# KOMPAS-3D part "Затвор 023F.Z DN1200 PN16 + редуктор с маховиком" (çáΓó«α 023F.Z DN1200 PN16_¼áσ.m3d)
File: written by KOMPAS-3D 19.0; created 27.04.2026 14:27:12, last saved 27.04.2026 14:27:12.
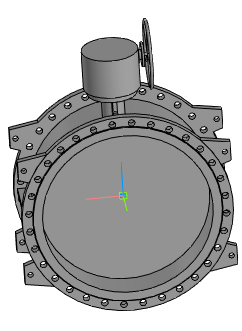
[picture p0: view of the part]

Document properties: Полное имя файла: ..\..\Затвор 023F.Z DN200-DN1600_с маховиком\Затвор 023F.Z DN1200 PN16 + редуктор с маховиком.a3d

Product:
- Part/product: Затвор 023F.Z DN1200 PN16 + редуктор с маховиком
    Масса: 2207.1

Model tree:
1. Операция без истории:1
